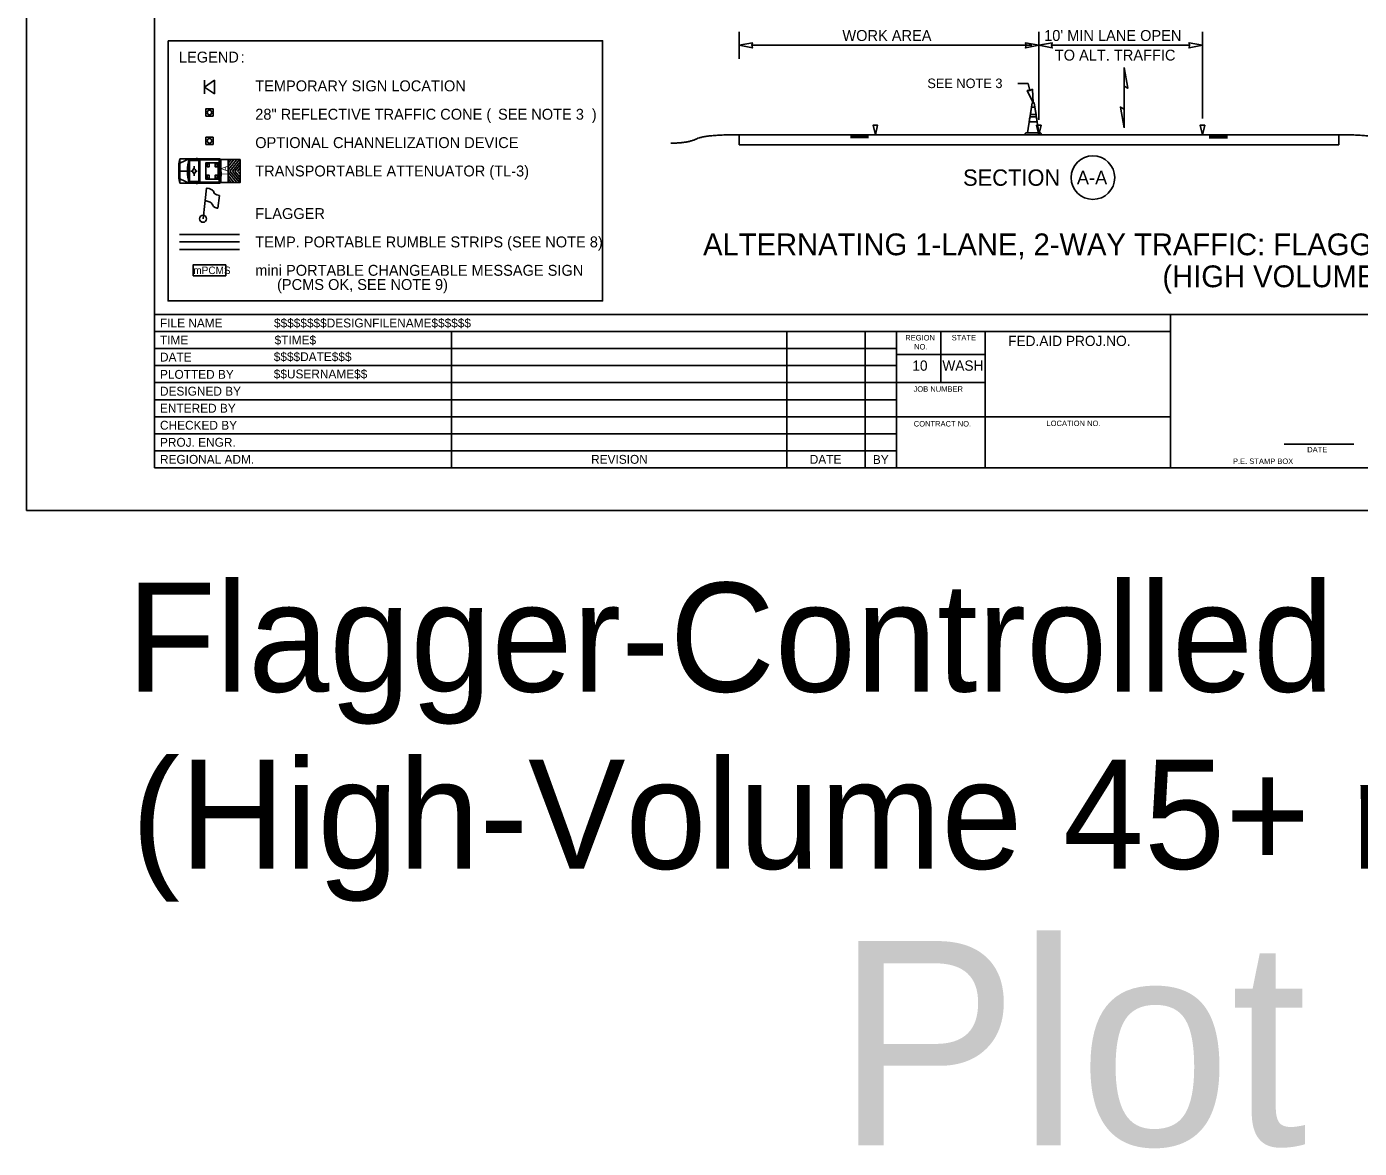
# Model space of a CAD drawing. Extents: x 99999.1 to 100095.7, y 99995 to 100010.7.
# Drawn here: x 100039.06 to 100048.84, y 99995.01 to 100003.24 of the extents above; entities that cross this region are included whole.
import ezdxf

# ---------------------------------------------------------------- set-up
doc = ezdxf.new("R2010")
doc.units = 0
for name, color, linetype in [('SH_DE_DetailHeading1Text', 7, 'Continuous'), ('SH_GI_PlotLimits', 7, 'Continuous'), ('SH_GI_SheetBorder', 7, 'Continuous'), ('SH_GI_SheetLocationText', 7, 'Continuous'), ('SH_GI_SheetTextInCells', 7, 'Continuous'), ('SH_GI_TitleBlockText', 7, 'Continuous'), ('TR_WZ_FlaggingStation', 7, 'Continuous'), ('TR_WZ_PCMS', 7, 'Continuous'), ('TR_WZ_PortableSignMountBlk-Org', 7, 'Continuous'), ('TR_WZ_TrafficCone', 7, 'Continuous'), ('TR_WZ_TrafficConeElev', 7, 'Continuous'), ('TR_WZ_TransportableAttenuator', 7, 'Continuous'), ('TR_WZ_WorkZoneDetails', 7, 'Continuous'), ('TR_WZ_WorkZoneTextCurrent', 7, 'Continuous')]:
    doc.layers.add(name, color=color, linetype=linetype)

msp = doc.modelspace()

# ---------------------------------------------------------------- linework, layer by layer
at = {"layer": 'SH_GI_PlotLimits'}
msp.add_lwpolyline([(100039.0625, 99999.6875), (100056.0625, 99999.6875), (100056.0625, 100010.6875), (100039.0625, 100010.6875)], close=True, dxfattribs=at)
at = {"layer": 'SH_GI_SheetBorder'}
for p, q in [((100040, 100010.375), (100040, 100000)), ((100040, 100001.1259), (100055.75, 100001.1259)), ((100047.4566, 100000), (100047.4566, 100001.1259)), ((100040, 100001.0008), (100047.4566, 100001.0008)), ((100042.179, 100001.0008), (100042.179, 100000)), ((100044.641, 100001.0008), (100044.641, 100000)), ((100045.2164, 100001.0008), (100045.2164, 100000)), ((100045.4451, 100001.0008), (100045.4451, 100000)), ((100045.7719, 100000.6255), (100045.7719, 100001.0008)), ((100046.0956, 100000), (100046.0956, 100001.0008)), ((100040, 100000.8757), (100042.1821, 100000.8757)), ((100042.1821, 100000.8757), (100045.4466, 100000.8757)), ((100046.0958, 100000.831), (100045.4466, 100000.831)), ((100040, 100000.7506), (100042.1821, 100000.7506)), ((100042.1821, 100000.7506), (100045.4466, 100000.7506)), ((100040, 100000.6255), (100045.4466, 100000.6255)), ((100046.0958, 100000.6255), (100045.4466, 100000.6255)), ((100040, 100000.5004), (100045.4466, 100000.5004)), ((100040, 100000.3753), (100045.4466, 100000.3753)), ((100047.4566, 100000.3753), (100045.4466, 100000.3753)), ((100040, 100000.2502), (100045.4466, 100000.2502)), ((100040, 100000.1251), (100045.4466, 100000.1251)), ((100048.2903, 100000.1733), (100048.802, 100000.1733)), ((100040, 100000), (100055.75, 100000))]:
    msp.add_line(p, q, dxfattribs=at)
at = {"layer": 'TR_WZ_FlaggingStation'}
for p, q in [((100040.3571, 100001.8286), (100040.3828, 100002.0533)), ((100040.3723, 100001.9621), (100040.3828, 100002.0536)), ((100040.3723, 100001.9621), (100040.3723, 100001.9621)), ((100040.4771, 100001.9993), (100040.4665, 100001.9056))]:
    msp.add_line(p, q, dxfattribs=at)
for points in [[(100040.3828, 100002.0536), (100040.3874, 100002.0525), (100040.4016, 100002.0498), (100040.4127, 100002.0465), (100040.4204, 100002.0416), (100040.4273, 100002.0378), (100040.4318, 100002.0324), (100040.4352, 100002.0261), (100040.4356, 100002.0211), (100040.4399, 100002.0138), (100040.4486, 100002.0078), (100040.4585, 100002.0036), (100040.4771, 100001.9993)], [(100040.4665, 100001.9056), (100040.46, 100001.9067), (100040.4458, 100001.9104), (100040.4333, 100001.9188), (100040.4281, 100001.9273), (100040.425, 100001.9355), (100040.4177, 100001.9442), (100040.4089, 100001.9492), (100040.395, 100001.9548), (100040.3723, 100001.9621)]]:
    msp.add_lwpolyline(points, dxfattribs=at)
msp.add_circle((100040.3571, 100001.8286), 0.026, dxfattribs=at)
at = {"layer": 'TR_WZ_PCMS'}
msp.add_lwpolyline([(100040.2841, 100001.41), (100040.5241, 100001.41), (100040.5241, 100001.49), (100040.2841, 100001.49)], close=True, dxfattribs=at)
msp.add_lwpolyline([(100040.2841, 100001.41), (100040.5241, 100001.41), (100040.5241, 100001.49), (100040.2841, 100001.49), (100040.2841, 100001.41)], dxfattribs=at)
at = {"layer": 'TR_WZ_PortableSignMountBlk-Org'}
msp.add_line((100040.3682, 100002.7454), (100040.3682, 100002.8454), dxfattribs=at)
msp.add_lwpolyline([(100040.3682, 100002.7953), (100040.44, 100002.8454), (100040.44, 100002.7454)], close=True, dxfattribs=at)
at = {"layer": 'TR_WZ_TrafficCone'}
for points in [[(100040.3775, 100002.6355), (100040.4308, 100002.6355), (100040.4308, 100002.5821), (100040.3775, 100002.5821), (100040.3775, 100002.6355)], [(100040.3775, 100002.5821), (100040.4308, 100002.5821), (100040.4308, 100002.6355), (100040.3775, 100002.6355), (100040.3775, 100002.5821)], [(100040.3775, 100002.4272), (100040.4308, 100002.4272), (100040.4308, 100002.3739), (100040.3775, 100002.3739), (100040.3775, 100002.4272)], [(100040.3775, 100002.3739), (100040.4308, 100002.3739), (100040.4308, 100002.4272), (100040.3775, 100002.4272), (100040.3775, 100002.3739)]]:
    msp.add_lwpolyline(points, dxfattribs=at)
for centre in [(100040.4041, 100002.6088), (100040.4041, 100002.4005)]:
    msp.add_circle(centre, 0.0167, dxfattribs=at)
at = {"layer": 'TR_WZ_TrafficConeElev'}
for p, q in [((100046.4363, 100002.6476), (100046.428, 100002.5934)), ((100046.4616, 100002.6476), (100046.4363, 100002.6476)), ((100046.4699, 100002.5934), (100046.4616, 100002.6476)), ((100046.4255, 100002.5768), (100046.4197, 100002.5393)), ((100046.4197, 100002.5393), (100046.4782, 100002.5393)), ((100046.4724, 100002.5768), (100046.4255, 100002.5768)), ((100046.428, 100002.5934), (100046.4699, 100002.5934)), ((100046.4782, 100002.5393), (100046.4724, 100002.5768)), ((100046.3953, 100002.458), (100046.3911, 100002.4538)), ((100046.3911, 100002.4538), (100046.3911, 100002.4455)), ((100046.3911, 100002.4455), (100046.5068, 100002.4455)), ((100046.4073, 100002.458), (100046.3953, 100002.458)), ((100046.5068, 100002.4538), (100046.5026, 100002.458)), ((100046.5068, 100002.4455), (100046.5068, 100002.4538))]:
    msp.add_line(p, q, dxfattribs=at)
msp.add_lwpolyline([(100046.4073, 100002.458), (100046.4906, 100002.458), (100046.4568, 100002.6788), (100046.4411, 100002.6788)], close=True, dxfattribs=at)
msp.add_lwpolyline([(100046.4073, 100002.458), (100046.4906, 100002.458), (100046.4568, 100002.6788), (100046.4411, 100002.6788)], close=True, dxfattribs=at)
msp.add_lwpolyline([(100046.5026, 100002.458), (100046.4906, 100002.458), (100046.4073, 100002.458)], dxfattribs=at)
at = {"layer": 'TR_WZ_TransportableAttenuator'}
for p, q in [((100040.186, 100002.269), (100040.1791, 100002.2327)), ((100040.186, 100002.089), (100040.186, 100002.269)), ((100040.186, 100002.269), (100040.3259, 100002.269)), ((100040.186, 100002.2361), (100040.256, 100002.269)), ((100040.256, 100002.089), (100040.256, 100002.269)), ((100040.2572, 100002.089), (100040.2572, 100002.269)), ((100040.2646, 100002.2551), (100040.2572, 100002.269)), ((100040.2572, 100002.2551), (100040.3259, 100002.2551)), ((100040.3068, 100002.2715), (100040.3152, 100002.2715)), ((100040.3259, 100002.089), (100040.3259, 100002.269)), ((100040.4803, 100002.269), (100040.3279, 100002.269)), ((100040.3279, 100002.089), (100040.3279, 100002.269)), ((100040.476, 100002.2618), (100040.3323, 100002.2618)), ((100040.3323, 100002.0962), (100040.3323, 100002.2618)), ((100040.476, 100002.0962), (100040.476, 100002.2618)), ((100040.4803, 100002.089), (100040.4803, 100002.269)), ((100040.4803, 100002.2633), (100040.5407, 100002.2633)), ((100040.4803, 100002.0946), (100040.4803, 100002.2633)), ((100040.4841, 100002.2661), (100040.4808, 100002.2661)), ((100040.4808, 100002.092), (100040.4808, 100002.2661)), ((100040.4874, 100002.0974), (100040.4874, 100002.2606)), ((100040.5407, 100002.1865), (100040.6046, 100002.2634)), ((100040.5407, 100002.2362), (100040.5637, 100002.2634)), ((100040.5839, 100002.2634), (100040.5407, 100002.2113)), ((100040.6046, 100002.2634), (100040.5407, 100002.1865)), ((100040.5407, 100002.2113), (100040.5839, 100002.2634)), ((100040.5637, 100002.2634), (100040.5407, 100002.2362)), ((100040.5407, 100002.2633), (100040.5407, 100002.0943)), ((100040.6234, 100002.2634), (100040.5531, 100002.1788)), ((100040.5531, 100002.1788), (100040.6234, 100002.2634)), ((100040.5637, 100002.2634), (100040.5839, 100002.2634)), ((100040.5839, 100002.2634), (100040.5637, 100002.2634)), ((100040.5728, 100002.1783), (100040.6291, 100002.2462)), ((100040.6291, 100002.2462), (100040.5728, 100002.1783)), ((100040.6046, 100002.2634), (100040.6234, 100002.2634)), ((100040.6234, 100002.2634), (100040.6046, 100002.2634)), ((100040.6291, 100002.2462), (100040.6291, 100002.2242)), ((100040.6291, 100002.2242), (100040.6291, 100002.2462)), ((100040.1791, 100002.1253), (100040.1791, 100002.2327)), ((100040.186, 100002.179), (100040.2422, 100002.179)), ((100040.2685, 100002.1789), (100040.2778, 100002.1789)), ((100040.2908, 100002.2147), (100040.2908, 100002.2001)), ((100040.2908, 100002.1434), (100040.2908, 100002.1579)), ((100040.3012, 100002.1793), (100040.3012, 100002.1793)), ((100040.3131, 100002.1789), (100040.3038, 100002.1789)), ((100040.4874, 100002.1917), (100040.4808, 100002.1883)), ((100040.4874, 100002.1663), (100040.4808, 100002.1697)), ((100040.4857, 100002.179), (100040.4826, 100002.179)), ((100040.4841, 100002.1765), (100040.4841, 100002.1816)), ((100040.5407, 100002.2113), (100040.5407, 100002.2362)), ((100040.5407, 100002.2362), (100040.5407, 100002.2113)), ((100040.5407, 100002.1714), (100040.5407, 100002.1865)), ((100040.5407, 100002.1865), (100040.5407, 100002.1714)), ((100040.6042, 100002.0943), (100040.5407, 100002.1714)), ((100040.5407, 100002.1714), (100040.6042, 100002.0943)), ((100040.5407, 100002.1465), (100040.5834, 100002.0943)), ((100040.5407, 100002.123), (100040.5407, 100002.1465)), ((100040.5834, 100002.0943), (100040.5407, 100002.1465)), ((100040.5407, 100002.1465), (100040.5407, 100002.123)), ((100040.5531, 100002.1788), (100040.6233, 100002.0943)), ((100040.6233, 100002.0943), (100040.5531, 100002.1788)), ((100040.6291, 100002.1104), (100040.5728, 100002.1783)), ((100040.5728, 100002.1783), (100040.6291, 100002.1104)), ((100040.6291, 100002.2242), (100040.5909, 100002.1781)), ((100040.5909, 100002.1781), (100040.6291, 100002.2242)), ((100040.5909, 100002.1781), (100040.6291, 100002.1323)), ((100040.6291, 100002.1323), (100040.5909, 100002.1781)), ((100040.6096, 100002.1787), (100040.6291, 100002.2023)), ((100040.6291, 100002.2023), (100040.6096, 100002.1787)), ((100040.6291, 100002.1555), (100040.6096, 100002.1787)), ((100040.6096, 100002.1787), (100040.6291, 100002.1555)), ((100040.6291, 100002.2023), (100040.6291, 100002.1555)), ((100040.6291, 100002.1555), (100040.6291, 100002.2023)), ((100040.186, 100002.089), (100040.1791, 100002.1253)), ((100040.186, 100002.122), (100040.256, 100002.089)), ((100040.186, 100002.089), (100040.3259, 100002.089)), ((100040.2572, 100002.089), (100040.2661, 100002.103)), ((100040.2572, 100002.103), (100040.3259, 100002.103)), ((100040.3068, 100002.0865), (100040.3152, 100002.0865)), ((100040.4803, 100002.089), (100040.3279, 100002.089)), ((100040.476, 100002.0962), (100040.3323, 100002.0962)), ((100040.4803, 100002.0943), (100040.5407, 100002.0943)), ((100040.4841, 100002.092), (100040.4808, 100002.092)), ((100040.5644, 100002.0943), (100040.5407, 100002.123)), ((100040.5407, 100002.123), (100040.5644, 100002.0943)), ((100040.5834, 100002.0943), (100040.5644, 100002.0943)), ((100040.5644, 100002.0943), (100040.5834, 100002.0943)), ((100040.6233, 100002.0943), (100040.6042, 100002.0943)), ((100040.6042, 100002.0943), (100040.6233, 100002.0943)), ((100040.6291, 100002.1323), (100040.6291, 100002.1104)), ((100040.6291, 100002.1104), (100040.6291, 100002.1323))]:
    msp.add_line(p, q, dxfattribs=at)
for points in [[(100040.5407, 100002.2634), (100040.6291, 100002.2634), (100040.6291, 100002.0943), (100040.5407, 100002.0943)], [(100040.4685, 100002.119), (100040.3785, 100002.119), (100040.3785, 100002.239), (100040.4685, 100002.239)], [(100040.386, 100002.209), (100040.401, 100002.209), (100040.401, 100002.2315), (100040.386, 100002.2315)], [(100040.386, 100002.1265), (100040.401, 100002.1265), (100040.401, 100002.149), (100040.386, 100002.149)], [(100040.461, 100002.209), (100040.446, 100002.209), (100040.446, 100002.2315), (100040.461, 100002.2315)], [(100040.461, 100002.1265), (100040.446, 100002.1265), (100040.446, 100002.149), (100040.461, 100002.149)]]:
    msp.add_lwpolyline(points, close=True, dxfattribs=at)
msp.add_lwpolyline([(100040.5407, 100002.0943), (100040.6291, 100002.0943), (100040.6291, 100002.2634), (100040.5407, 100002.2633)], dxfattribs=at)
for centre, major_axis, start_param, end_param in [((100040.3559, 100002.179), (0, -0.1889), 4.215852, 5.209111), ((100040.4841, 100002.2606), (0, 0.00549), 4.712389, 6.283185), ((100040.4841, 100002.0975), (0, -0.00549), 6.283185, 7.853982)]:
    msp.add_ellipse(centre, major_axis=major_axis, ratio=0.60201, start_param=start_param, end_param=end_param, dxfattribs=at)
for centre, major_axis in [((100040.2908, 100002.179), (0, 0.0173)), ((100040.4841, 100002.179), (0, 0.00254))]:
    msp.add_ellipse(centre, major_axis=major_axis, ratio=0.60201, dxfattribs=at)
at = {"layer": 'TR_WZ_WorkZoneDetails'}
for p, q in [((100044.2907, 100003.0015), (100044.2907, 100003.2015)), ((100046.4907, 100002.5552), (100046.4907, 100003.2015)), ((100047.6907, 100002.5652), (100047.6907, 100003.2015)), ((100046.4387, 100003.1015), (100044.3844, 100003.1015)), ((100047.597, 100003.1015), (100046.5844, 100003.1015)), ((100046.3358, 100002.8215), (100046.412, 100002.8215)), ((100046.4255, 100002.7696), (100046.412, 100002.8215)), ((100047.1157, 100002.8019), (100047.1157, 100002.6331)), ((100047.1157, 100002.6331), (100047.1157, 100002.8019)), ((100044.2907, 100002.4454), (100044.2907, 100002.3704)), ((100048.6907, 100002.4454), (100044.2907, 100002.4454)), ((100045.1077, 100002.4402), (100045.2407, 100002.4402)), ((100047.8737, 100002.4398), (100047.7407, 100002.4398)), ((100048.6907, 100002.4454), (100048.6907, 100002.3704)), ((100048.6907, 100002.3704), (100044.2907, 100002.3704)), ((100045.1077, 100002.4346), (100045.2407, 100002.4346)), ((100045.1077, 100002.4289), (100045.2407, 100002.4289)), ((100045.1077, 100002.4237), (100045.2407, 100002.4237)), ((100047.8737, 100002.4342), (100047.7407, 100002.4342)), ((100047.8737, 100002.4285), (100047.7407, 100002.4285)), ((100047.8737, 100002.4233), (100047.7407, 100002.4233)), ((100040.6241, 100001.7135), (100040.1841, 100001.7135)), ((100040.6241, 100001.6587), (100040.1841, 100001.6587)), ((100040.6241, 100001.603), (100040.1841, 100001.603))]:
    msp.add_line(p, q, dxfattribs=at)
for points in [[(100044.2907, 100003.1015), (100044.389, 100003.0822), (100044.3844, 100003.1015), (100044.389, 100003.1208)], [(100046.4907, 100003.1015), (100046.3924, 100003.0822), (100046.397, 100003.1015), (100046.3924, 100003.1208)], [(100046.4907, 100003.1015), (100046.589, 100003.0822), (100046.5844, 100003.1015), (100046.589, 100003.1208)], [(100047.6907, 100003.1015), (100047.5924, 100003.0822), (100047.597, 100003.1015), (100047.5924, 100003.1208)], [(100047.1157, 100002.9395), (100047.1427, 100002.7863), (100047.1157, 100002.8019)], [(100046.449, 100002.6788), (100046.4057, 100002.7692), (100046.4255, 100002.7696), (100046.443, 100002.7788)], [(100047.1157, 100002.4954), (100047.0887, 100002.6487), (100047.1157, 100002.6331)], [(100045.2907, 100002.4454), (100045.274, 100002.5152), (100045.3073, 100002.5152)], [(100046.4907, 100002.4454), (100046.474, 100002.5152), (100046.5074, 100002.5152)], [(100047.6907, 100002.4454), (100047.674, 100002.5152), (100047.7073, 100002.5152)]]:
    msp.add_lwpolyline(points, close=True, dxfattribs=at)
for points in [[(100045.3073, 100002.5152), (100045.274, 100002.5152), (100045.2907, 100002.4454), (100045.3073, 100002.5152)], [(100046.5074, 100002.5152), (100046.474, 100002.5152), (100046.4907, 100002.4454), (100046.5074, 100002.5152)], [(100047.7073, 100002.5152), (100047.674, 100002.5152), (100047.6907, 100002.4454), (100047.7073, 100002.5152)]]:
    msp.add_lwpolyline(points, dxfattribs=at)
msp.add_circle((100046.8872, 100002.1305), 0.16, dxfattribs=at)
for points in [[(100044.2907, 100002.4454), (100044.0395, 100002.4454), (100043.914, 100002.3833), (100043.7886, 100002.3833)], [(100048.6907, 100002.4454), (100048.9419, 100002.4456), (100049.0674, 100002.3835), (100049.1928, 100002.3836)]]:
    msp.add_open_spline(points, degree=2, dxfattribs=at)
at = {"layer": 'TR_WZ_WorkZoneTextCurrent'}
msp.add_lwpolyline([(100040.1, 100003.1351), (100043.2886, 100003.1351), (100043.2886, 100001.2259), (100040.1, 100001.2259)], close=True, dxfattribs=at)

# ---------------------------------------------------------------- texts
at = {"layer": 'SH_DE_DetailHeading1Text'}
for s, p in [('ALTERNATING 1-LANE, 2-WAY TRAFFIC: FLAGGER-CONTROLLED + TEMPORARY RUMBLE STRIPS', (100044.0265, 100001.5606)), ('(HIGH VOLUME 45+ MPH HIGHWAYS)', (100047.3973, 100001.3259))]:
    msp.add_text(s, height=0.16, rotation=360, dxfattribs=at).set_placement(p)
at = {"layer": 'SH_GI_SheetLocationText'}
for s, height, p in [('Flagger-Controlled Alt Traffic + RS', 0.8, (100039.7975, 99998.3571)), ('(High-Volume 45+ mph Highways)', 0.8, (100039.8302, 99997.0571)), ('Plot 3', 1.5, (100045.0008, 99995.0267))]:
    msp.add_text(s, height=height, dxfattribs=at).set_placement(p)
at = {"layer": 'SH_GI_SheetTextInCells'}
for s, height, p in [('FILE NAME', 0.06505, (100040.041, 100001.0308)), ('TIME', 0.06505, (100040.041, 100000.9057)), ('REGION', 0.04003, (100045.5099, 100000.9352)), ('STATE', 0.04003, (100045.8511, 100000.9357)), ('FED.AID PROJ.NO.', 0.07506, (100046.2652, 100000.8945)), ('NO.', 0.04003, (100045.5752, 100000.869)), ('DATE', 0.06505, (100040.041, 100000.7806)), ('10', 0.07506, (100045.5621, 100000.7131)), ('WASH', 0.07506, (100045.7826, 100000.7131)), ('PLOTTED BY', 0.06505, (100040.041, 100000.6538)), ('DESIGNED BY', 0.065052, (100040.041, 100000.5304)), ('JOB NUMBER', 0.04003, (100045.5712, 100000.5587)), ('ENTERED BY', 0.06505, (100040.041, 100000.4053)), ('CHECKED BY', 0.06505, (100040.041, 100000.2802)), ('CONTRACT NO.', 0.040032, (100045.5725, 100000.3037)), ('LOCATION NO.', 0.040032, (100046.5465, 100000.3067)), ('PROJ. ENGR.', 0.065052, (100040.041, 100000.1551)), ('REGIONAL ADM.', 0.065052, (100040.041, 100000.03)), ('REVISION', 0.06505, (100043.2048, 100000.03)), ('DATE', 0.06505, (100044.8091, 100000.03)), ('BY', 0.06505, (100045.2725, 100000.0285)), ('DATE', 0.04003, (100048.4597, 100000.1141)), ('P.E. STAMP BOX', 0.040032, (100047.915, 100000.0286))]:
    msp.add_text(s, height=height, dxfattribs=at).set_placement(p)
at = {"layer": 'SH_GI_TitleBlockText'}
for s, height, p in [('$$$$$$$$DESIGNFILENAME$$$$$$', 0.065052, (100040.8775, 100001.0308)), ('$TIME$', 0.06505, (100040.882, 100000.9059)), ('$$$$DATE$$$', 0.065052, (100040.8759, 100000.7835)), ('$$USERNAME$$', 0.065052, (100040.8759, 100000.6567))]:
    msp.add_text(s, height=height, dxfattribs=at).set_placement(p)
at = {"layer": 'TR_WZ_PCMS'}
msp.add_text('mPCMS', height=0.055, rotation=360, dxfattribs=at).set_placement((100040.2856, 100001.4225))
at = {"layer": 'TR_WZ_TransportableAttenuator'}
msp.add_text('TA', height=0.045, rotation=89.99999, dxfattribs=at).set_placement((100040.5366, 100002.1395))
at = {"layer": 'TR_WZ_WorkZoneDetails'}
for s, p in [('WORK AREA', (100045.0487, 100003.1335)), ("10' MIN LANE OPEN", (100046.5294, 100003.1335)), ('TO ALT. TRAFFIC', (100046.6075, 100002.9895))]:
    msp.add_text(s, height=0.08, dxfattribs=at).set_placement(p)
for s, height, p in [('SECTION', 0.12, (100045.9342, 100002.0705)), ('A-A', 0.1, (100046.7694, 100002.0805))]:
    msp.add_text(s, height=height, rotation=360, dxfattribs=at).set_placement(p)
at = {"layer": 'TR_WZ_WorkZoneTextCurrent'}
for s, p in [('LEGEND', (100040.18, 100002.9751)), (':', (100040.6328, 100002.9751)), ('TEMPORARY SIGN LOCATION ', (100040.74, 100002.7639)), ('28" REFLECTIVE TRAFFIC CONE (', (100040.74, 100002.5556)), ('SEE NOTE 3', (100042.5216, 100002.5556)), (')', (100043.2099, 100002.5556)), ('OPTIONAL CHANNELIZATION DEVICE', (100040.74, 100002.3473)), ('TRANSPORTABLE ATTENUATOR (TL-3)', (100040.74, 100002.139)), ('FLAGGER', (100040.74, 100001.8266)), ('TEMP. PORTABLE RUMBLE STRIPS (SEE NOTE 8)', (100040.74, 100001.6183)), ('mini PORTABLE CHANGEABLE MESSAGE SIGN', (100040.74, 100001.41)), ('(PCMS OK, SEE NOTE 9)', (100040.9, 100001.3059))]:
    msp.add_text(s, height=0.08, rotation=360, dxfattribs=at).set_placement(p)
msp.add_text('SEE NOTE 3', height=0.07, dxfattribs=at).set_placement((100045.672, 100002.7875))

doc.saveas('drawing.dxf')
